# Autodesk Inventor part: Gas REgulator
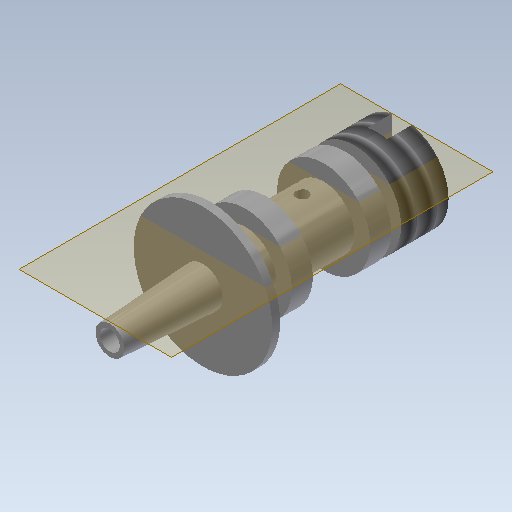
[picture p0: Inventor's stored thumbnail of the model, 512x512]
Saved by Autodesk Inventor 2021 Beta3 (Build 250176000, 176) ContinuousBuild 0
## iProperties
Created: 2012-08
Part Number: Gas REgulator
Material: Steel
Document SubType Name: Modeling
Designer: John
Mass: 2.31366 g
Surface Area: 5.19713 cm^2
Volume: 0.294733 cm^3
Density: 7.85 g/cm^3
Appearance: Steel
Author: John
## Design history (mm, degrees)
sketch "Sketch1"
  geometry: L1 (0, 0)-(0.927, 0); L2 (0.927, 0)-(1.27, -5.969); L3 (1.27, -5.969)-(4.445, -5.969); L4 (4.445, -5.969)-(4.445, -6.477); L5 (4.445, -6.477)-(2.985, -6.477); L6 (2.985, -6.477)-(2.985, -7.544); L7 (2.985, -7.544)-(1.969, -7.544); L8 (1.969, -7.544)-(1.969, -8.687); L9 (1.969, -8.687)-(2.985, -8.687); L10 (2.985, -8.687)-(2.985, -10.033); L11 (2.985, -10.033)-(1.969, -10.033); L12 (1.969, -10.033)-(1.969, -13.716); L13 (1.969, -13.716)-(2.985, -13.716); L14 (2.985, -13.716)-(2.985, -15.062); L15 (2.985, -15.062)-(1.969, -15.062); L16 (1.969, -15.062)-(1.969, -15.697); L17 (1.969, -15.697)-(2.985, -15.697); L18 (2.985, -15.697)-(2.985, -18.745); L19 (2.985, -18.745)-(0, -18.745); L20 (0, -18.745)-(0, 0); L21 (0, 0)-(0, 8.189)
  constraints: 42 end point, 10 parallel, 8 perpendicular, 6 collinear, 1 horizontal
  dimensions: "d2" = 1.8542 diameter of L1.end L21; "d4" = 5.969 distance between parallel lines of L3 L1; "d5" = 6.477 distance between parallel lines of L1 L5; "d6" = 7.5438 distance between parallel lines of L1 L7; "d7" = 8.6868 distance between parallel lines of L1 L9; "d8" = 10.033 distance between parallel lines of L1 L11; "d9" = 13.716 distance between parallel lines of L1 L13; "d10" = 15.0622 distance between parallel lines of L15 L1; "d11" = 0.635 distance between parallel lines of L17 L15; "d12" = 18.7452 distance between parallel lines of L1 L19; "d13" = 5.969 diameter of L18 L21; "d14" = 8.89 diameter of L4 L21; "d15" = 3.937 diameter of L16 L21; "d16" = 2.54 diameter of L2.end L21
revolve "Revolution1" sketch "Sketch1" stored, may be unused: angle "d17" = 90 deg
sketch "Sketch2"
  geometry: C1 r 0.927 at (0, 0) reference
hole "Hole1" sketch "Sketch2" at (0, 0) diameter "d18" = 1.27; stored, may be unused: countersink angle "d22" = 82 deg, drill point angle "d24" = 118 deg; dims "d19" = 19.05, "d20" = 9.525, "d21" = 6.35, "d23" = 12.319
workplane "Work Plane1"
sketch "Sketch3"
  geometry: L1 (-0.927, 11.875)-(0.927, 11.875) reference; L2 (0, 11.875)-(0, -0.444)
  constraints: 2 end point, 1 perpendicular
  dimensions: "d25" = 12.319 distance of L2.start L2.end
hole "Hole2" sketch "Sketch3" at (0, -0.444) diameter "d26" = 0.7874; stored, may be unused: countersink angle "d30" = 82 deg, drill point angle "d32" = 118 deg; dims "d27" = 19.05, "d28" = 9.525, "d29" = 6.35, "d31" = 12.319
thread "Thread1" dims "d33" = 25.4, "d34" = 0
sketch "Sketch4"
  geometry: L1 (-0.635, 2.985)-(0.635, 2.985); L2 (0.635, 2.985)-(0.635, -2.985); L3 (0.635, -2.985)-(-0.635, -2.985); L4 (-0.635, -2.985)-(-0.635, 2.985); C1 r 2.985 at (0, 0) reference
  constraints: 8 end point, 2 parallel, 2 tangent, 1 horizontal, 1 perpendicular
  dimensions: "d35" = 1.27 distance of L1.start L1.end; "d37" = 0.635 distance from line of C1.centre L2 (= 0.5 x d35)
extrude "Extrusion1" cut sketch "Sketch4" distance "d38" = 1.5875; taper "d39" = 0 deg
body "Solid1"
